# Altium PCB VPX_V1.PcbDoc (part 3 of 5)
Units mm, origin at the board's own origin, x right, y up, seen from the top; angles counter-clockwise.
Board outline 157.76 x 100.08 mm, 10 copper layers (Top Layer (PADS/SIG), Layer 2 (GND), Layer 3 (SIG), Layer 4 (SIG), Layer 5 (GND), Layer 6 (PWR), Layer 7 (GND), Layer 8 (SIG/PWR), Layer 9 (GND), Bottom Layer (PAD/SIG)), stack 1.614 mm thick; 383 components, 223 nets, 1313 pads, 1223 vias.
Unrouted connection lines stored in the file: 3.
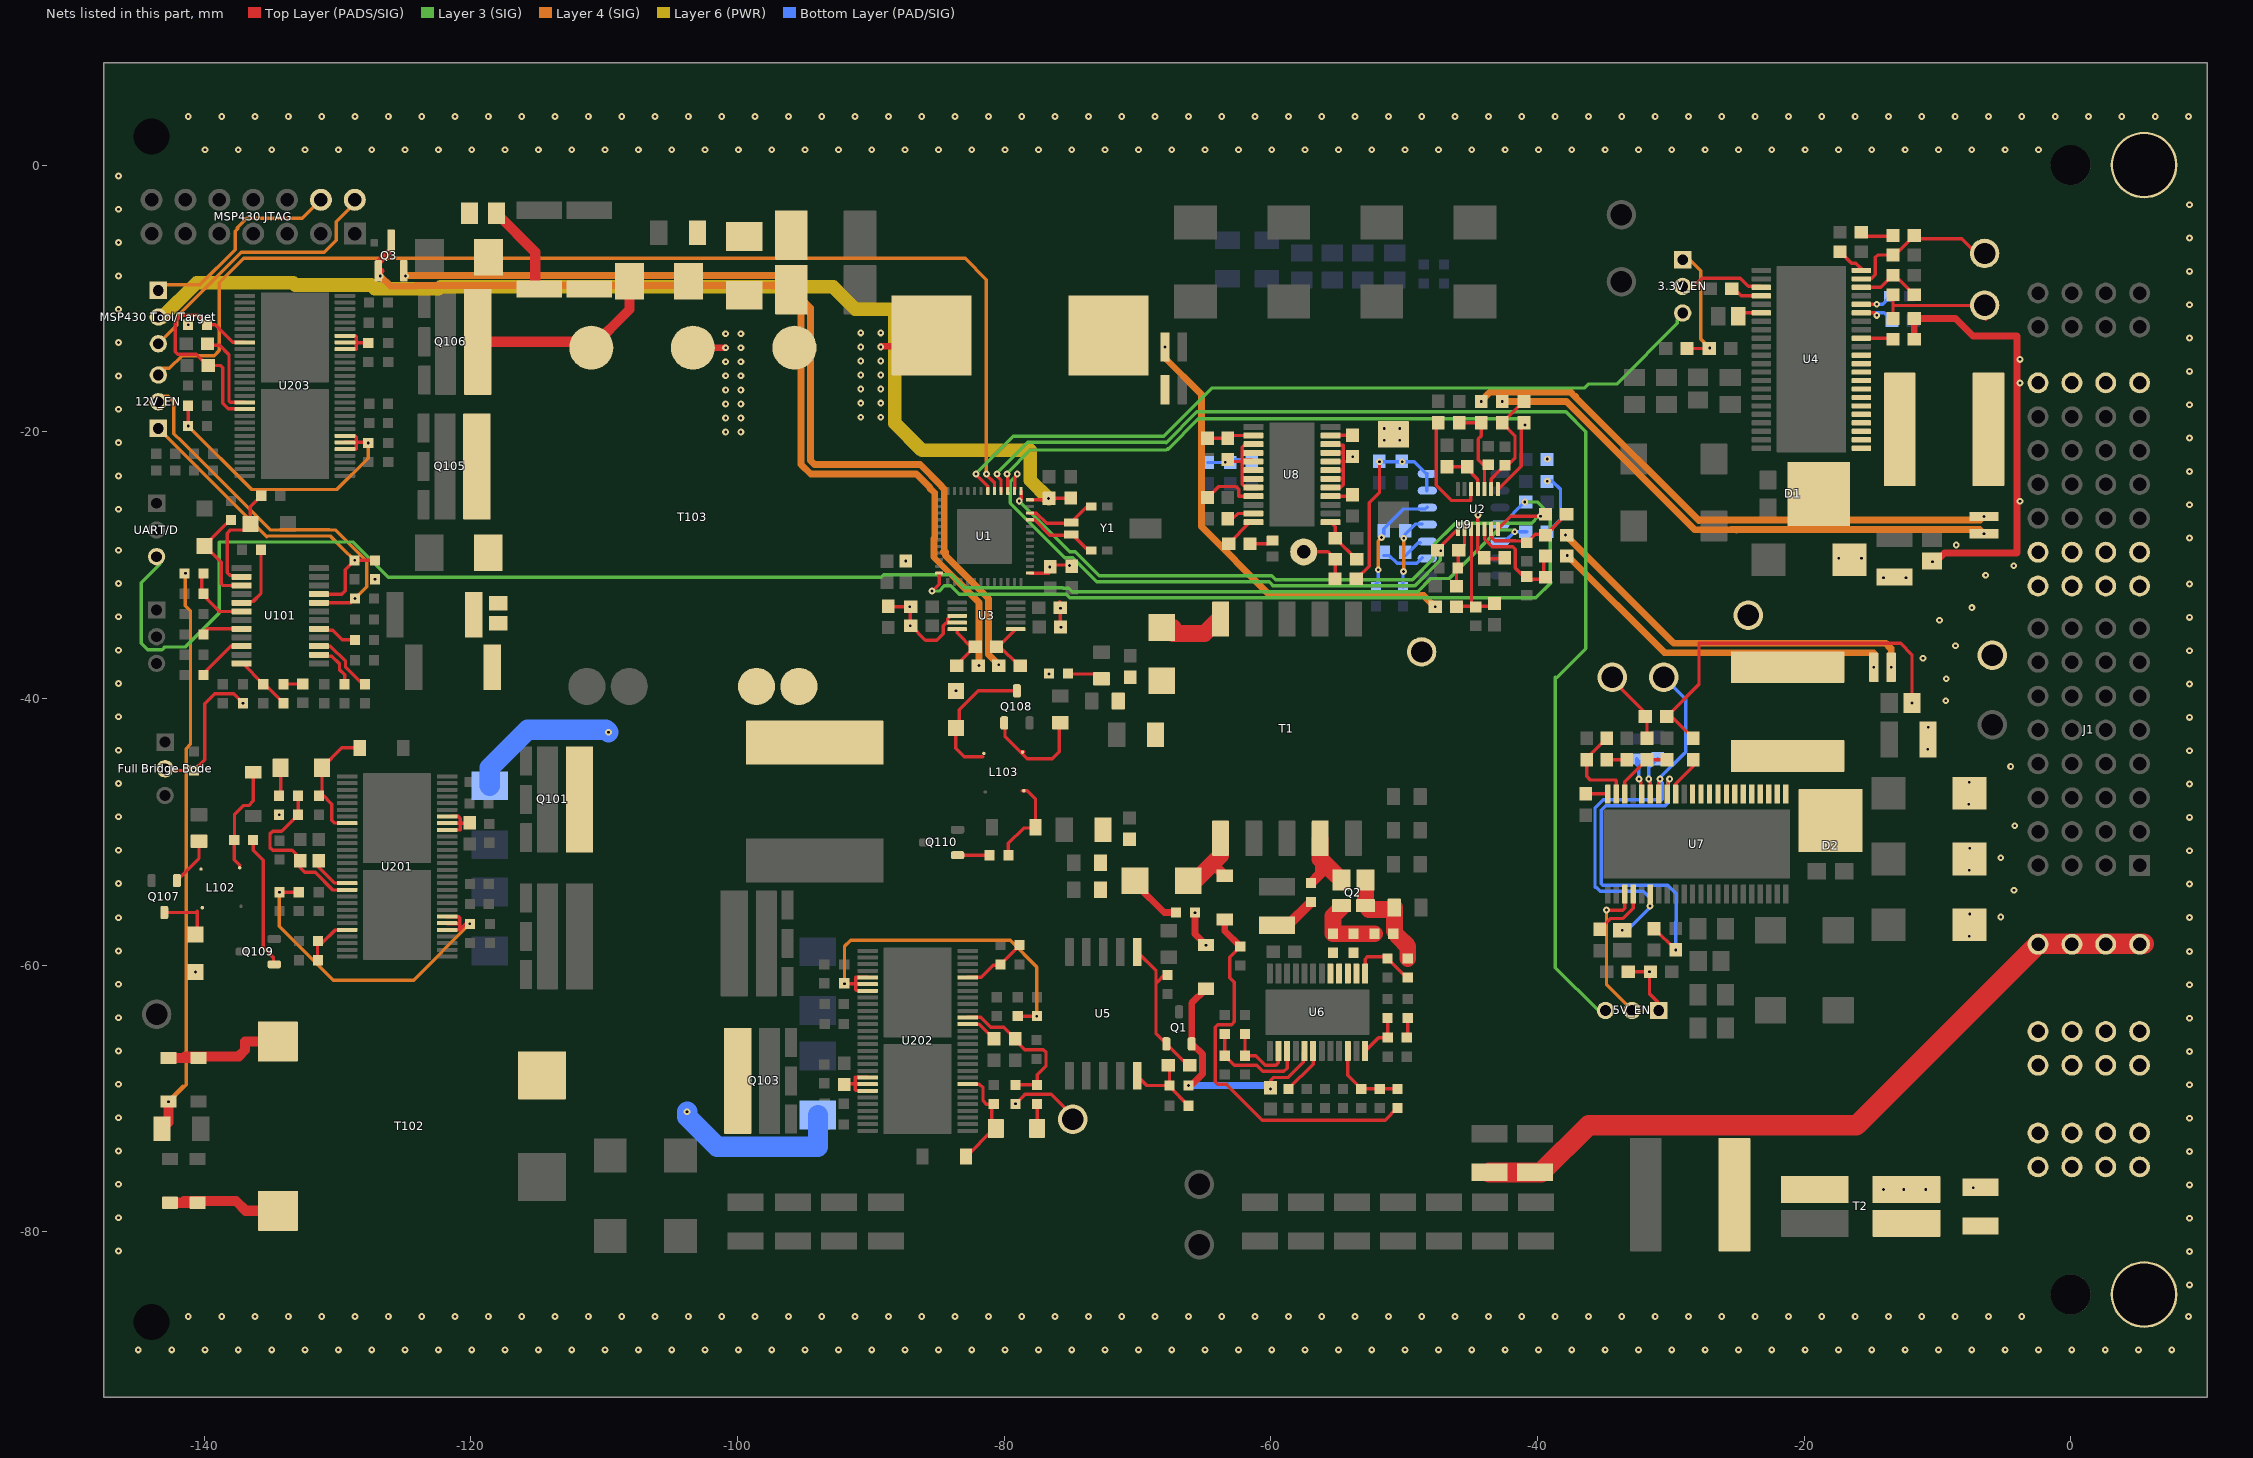
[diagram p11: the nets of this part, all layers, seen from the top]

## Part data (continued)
T1: library part CMP-0123192-1, "Transformer", Frequency_Fixed=500kHz, Manufacturer=Coilcraft, Operating Temperature Range=to, Voltage_Isolation_Vrms=2500Vrms
T2: library part CMP-0081219-1, "Coupled inductor, 0.001 ohm, AEC-Q200 Grade 1, SMD", Manufacturer="Laird-Signal Integrity Products", Supplier Part Number 1=240-2463-1-ND
T102: library part CMP-0122471-1, "Current Transformer 1:50", Manufacturer="Payton Planar", Operating Temperature Range=to
T103: library part CMP-0122726-1, "Transformer Vin-22-36V/500KHz/Full-Bridge, Vo=12V/26A Isolation=1500V, T/R=3:2", Manufacturer=Coilcraft, Operating Temperature Range=to, Voltage_Isolation_Vrms=1.5kV
U1: library part CMP-0066503-2, "MSP430FR5969 16 MHz Ultra-Low-Power Microcontroller featuring 64 KB FRAM, 2 KB SRAM, 40 IO, RGZ0048B (VQFN-48)", Alternate Manufacturer="Texas Instruments", Alternate PartNumber=MSP430FR5969IRGZT
U2: library part CMP-0037180-1, "Space-enhanced-product, quad, 40-V 4.5-MHz rail-to-rail input and output operational amplifier 14-SOT-23-THIN -55 to +125", Digikey Part Number=296-OPA4H199MDYYTSEP-ND, Input Bias Current=0.00001uA, Input Offset Voltage=0.125mV, Manufacturer="Texas Instruments", Max Dual Supply Voltage=20V, Max Supply Voltage=40V, Min Dual Supply Voltage=1.35V, Min Supply Voltage=2.7V, Mouser Part Number=595-OPA4H199MDYYTSEP, Nominal Supply Current=560uA, Operating Temperature Range="-55°C to +125°C", Output Current Per Channel=75mA, Voltage Gain=145dB
U3: library part CMP-0121240-1, "High-Accuracy, Radiation-Hardness-Assured (RHA) Remote and Local Temperature Sensor", Manufacturer="Texas Instruments", Max Supply Voltage=3.6V, Min Supply Voltage=1.7V, Operating Supply Current=3-400uA, Operating Temperature Range="-55°C to +125°C"
U4: library part CMP-0124169-1, "4.5V to 14V Input, 3A, Radiation Hardened Synchronous Buck Converter", Manufacturer="Texas Instruments", Max Supply Voltage=14V, Min Supply Voltage=4.5V, Nominal Supply Current=2.6mA, Operating Temperature Range="-55°C to +125°C", Switching Frequency=100-1000kHz
U5: library part CMP-0093806-3, "Radiation-hardness-assured (RHA) 0.4% accuracy, 2.4-V to 36-V adjustable shunt reference 10-CFP 25 to 25", Manufacturer="Texas Instruments", Max Supply Voltage=36V, Min Supply Voltage=2.475V, Mouser Part Number=595-TL1431U/EM, Operating Temperature Range="-55°C to +125°C", Output Voltage=2.5-36V
U6: library part CMP-0122233-2, "Radiation-Hardness-Assured 1-MHz Current Mode PWM Controller with Integrated Gate Driver", Manufacturer="Texas Instruments", Max Supply Voltage=14V, Min Supply Voltage=4.5V, Nominal Supply Current=5-22mA, Operating Temperature Range="-55°C to +125°C"
U7: library part CMP-0121219-1, "4.5-V to 14-V Input 12-A Radiation Hardened Synchronous Buck Converter", Manufacturer="Texas Instruments", Max Supply Voltage=14V, Min Supply Voltage=4.5V, Nominal Supply Current=8mA, Operating Temperature Range="-55°C to +125°C", Switching Frequency=100-1000kHz
U8: library part CMP-0122232-1, "2.25 V to 14-V Input, 2-A, Radiation Hardened LDO Regulator", Dropout Voltage=1000mV, Manufacturer="Texas Instruments", Max Supply Voltage=14V, Min Supply Voltage=2.25V, Nominal Supply Current=8-10mA, Operating Temperature Range="-55°C to +125°C", Output Voltage=0.6-13.9V
U9: library part CMP-0081980-1, "3.3-V to 5-V RS-485 Transceivers With +/-18-kV IEC ESD Protection, D0014A (SOIC-14)", Alternate Manufacturer="Texas Instruments", Alternate PartNumber=THVD1452DR, Operating Temperature Range="-40 to 125 C"
U101: library part CMP-0092938-1, Manufacturer="Texas Instruments", Operating Temperature Range=to
U201 U202: library part CMP-0120202-4, Manufacturer="Texas Instruments", Operating Temperature Range=to, PartNumber=TPS7H6015MDCATSEP
U203: library part CMP-0120202-4, Manufacturer="Texas Instruments", Operating Temperature Range=to, PartNumber=TPS7H6025MDCATSEP
Y1: library part CMP-0004695-4, "Crystal, 32.768 KHz, 7pF, SMD", Frequency_Fixed=32.768kHz, Load Capacitance="7 pF", Manufacturer="Micro Crystal AG"

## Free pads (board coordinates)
  round 1.524 hole 2.7 unplated: 3(-143.947,2.13) 4(-143.947,-86.77)

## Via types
v1: diameter 0.508, hole 0.203, Top Layer (PADS/SIG) to Bottom Layer (PAD/SIG), 943 vias
v2: diameter 0.5, hole 0.2, Top Layer (PADS/SIG) to Bottom Layer (PAD/SIG), tented both sides, 268 vias
v3: diameter 0.5, hole 0.2, Top Layer (PADS/SIG) to Bottom Layer (PAD/SIG), 12 vias

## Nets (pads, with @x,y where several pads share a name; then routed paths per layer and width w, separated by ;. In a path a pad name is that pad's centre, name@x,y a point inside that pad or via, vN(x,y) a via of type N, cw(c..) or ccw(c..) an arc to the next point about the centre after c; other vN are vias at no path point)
3.3_CurrentSense: R15.1 U1.3 U2.8 | length 47.8
  Top Layer (PADS/SIG) w0.254: U1.3@-79.718,-24.453 v1@-79.718,-23.162 ; U2.8@-42.969,-24.305 -42.926,-24.305 -41.275,-22.654 -41.275,-22.606 ; -41.221,-22.6 -41.221,-19.504 R15.1@-41.021,-19.304
  Layer 3 (SIG) w0.254: v1(-79.776,-23.172) -79.776,-23.123 -78.021,-21.368 -67.826,-21.368 -67.734,-21.276 ; -67.7,-21.31 -65.426,-19.036 -41.399,-19.036 v1(-40.937,-19.498)
3.3V: "MSP430 Tool/Target.2" C3.1 C4.1 C60.2 C88.1 C89.1 C99.2 C100.1 C126.1 R18.1 R19.1 R20.1 R21.1 R22.2 R24.1 R25.1 R26.1 R31.2 R80.1 U1.37 U1.48 U3.3 U3.4 U8.17 U8.18 U8.19 U8.20 U8.21 U8.22 U9.13 U9.14 | length 126
  Top Layer (PADS/SIG) w0.254: C60.2@-88.689,-33.087 -88.649,-33.128 v1(-87.069,-33.128) ; v1(-87.038,-34.542) R19.1@-87.038,-33.128 ; R18.1@-87.009,-34.513 -85.895,-35.627 -85.042,-35.627 -84.566,-35.151 -84.566,-34.556 -84.369,-34.359 ; -84.244,-34.336 -84.244,-34.057 -84,-33.813 U3.3@-83.514,-33.813 ; U1.37@-78.068,-30.603 C3.1@-76.655,-30.603 ; U1.48@-78.068,-25.103 -76.751,-25.103 v1(-76.661,-25.014) C88.1@-76.63,-24.982 -75.368,-24.982 C89.1@-75.147,-25.203 ; v1(-76.576,-30.154) -76.416,-29.994 -75.062,-29.994 -75.062,-30.001 v1(-75.1,-30.039) ; R20.1@-75.887,-33.231 R20.1@-75.887,-33.049 ; R20.1@-75.83,-33.231 R20.1@-75.83,-32.763 ; R21.1@-75.792,-34.511 R20.1@-75.792,-33.184 ; U8.17@-55.506,-24.188 -54.778,-24.188 -54.573,-23.983 -54.573,-23.51 ; U8.18@-55.506,-23.538 -54.601,-23.538 -54.573,-23.51 ; U8.19@-55.506,-22.888 -54.598,-22.888 -54.573,-22.863 ; U8.20@-55.506,-22.238 -54.573,-22.238 ; U8.21@-55.506,-21.588 -54.649,-21.588 -54.573,-21.664 ; U8.22@-55.034,-21.022 -54.573,-21.022 -54.573,-21.664 ; v1(-53.839,-21.888) -54.189,-22.238 -54.573,-22.238 ; R31.2@-53.58,-31.036 -52.621,-30.077 -52.621,-25.34 -51.859,-24.578 ; -51.84,-24.578 v1(-51.84,-22.254) ; -54.573,-23.51 -54.573,-22.863 ; -54.573,-22.863 -54.573,-22.238 ; -54.573,-22.238 -54.573,-21.664
  Layer 6 (PWR) w1.016: -143.426,-11.402 -143.125,-11.402 -140.553,-8.83 -133.305,-8.83 -133.139,-8.996 -127.475,-8.996 -127.187,-9.284 -122.38,-9.284 -122.234,-9.138 -92.822,-9.138 -91.148,-10.811 -88.181,-10.811 -88.181,-19.371 -86.149,-21.403 -78.041,-21.403 ; -78.021,-21.403 -78.041,-21.403 ; v1(-76.661,-25.014) -78.041,-23.634 -78.041,-21.403
  Bottom Layer (PAD/SIG) w0.254: v1(-51.84,-22.254) v1(-50.138,-22.254) -49.23,-22.254 U9.14@-48.303,-23.181 ; U9.13@-48.303,-24.451 -48.303,-23.197 U9.14@-48.259,-23.154 ; R80.1@-39.286,-27.626 R80.1@-39.253,-27.594 ; R80.1@-39.286,-27.499 -39.159,-27.499 -38.27,-26.61 -38.27,-24.324 -38.887,-23.707 v1(-39.253,-23.707)
  other v1: -75.737,-34.676 -75.766,-33.231 -87.383,-29.694 -39.253,-22.048 -51.478,-20.641 -50.335,-20.641 -51.478,-19.752 -50.335,-19.752
"3.3V CS+": L1.2 R3.1 R12.2 | length 42.5
  Top Layer (PADS/SIG) w0.508: v1(-6.515,-26.355) R3.1@-6.134,-26.355
  Layer 4 (SIG) w0.508: v1(-44.218,-17.732) -44.218,-17.699 -43.543,-17.024 -37.526,-17.024 -37.211,-17.339 ; -37.127,-17.339 -37.211,-17.339 ; -27.898,-26.652 -37.211,-17.339 ; -27.856,-26.61 -27.836,-26.63 -6.79,-26.63 v1(-6.515,-26.355)
3.3V_EN: 3.3V_EN.3 U1.6 | length 59.2
  Top Layer (PADS/SIG) w0.254: v1(-82.097,-23.172) -82.097,-23.22 -81.218,-24.098 U1.6@-81.218,-24.453
  Layer 3 (SIG) w0.254: v1(-82.097,-23.172) -82.097,-23.123 -79.324,-20.351 -68.024,-20.351 ; -68.03,-20.345 -64.41,-16.726 -36.482,-16.726 -36.182,-16.426 -34.055,-16.426 -29.507,-11.878 -29.507,-11.624
3.3V_OUT: 3.3V_Out.1 C25.1 C27.1 C29.1 J1.LP2 R3.2 R14.2 R35.1 R37.1 | length 73.4
  Top Layer (PADS/SIG) w0.508: R35.1@-11.738,-13.062 R37.1@-11.738,-11.509 -8.648,-11.509 -7.325,-12.833 -4.044,-12.833 -4.044,-29.1 -4.039,-29.105 -9.463,-29.105 -10.059,-29.701 C29.1@-10.401,-29.701
  Layer 4 (SIG) w0.508: v1@-42.582,-17.793 v1(-42.643,-17.732) -37.819,-17.732 -28.191,-27.36 -25.074,-27.36 -25.062,-27.372 ; -25.488,-27.338 -6.831,-27.338 v1(-6.515,-27.655)
  other v1: -14.054,-30.944 -12.361,-30.944 -10.367,-29.76 -17.394,-29.501 -15.701,-29.501 -8.582,-28.499 -3.807,-25.208 -3.807,-16.354 -3.807,-14.575
5V: 5V.1 C15.1 C66.1 C67.1 C68.1 C70.1 J1.P3 R9.2 R32.2 R41.1 R67.1 | length 58.4
  Top Layer (PADS/SIG) w0.254: R41.1@-28.315,-42.99 -29.94,-41.365 R67.1@-30.303,-41.365 -27.882,-38.944 -27.882,-35.877 -12.761,-35.877 -11.911,-36.727 v1(-11.911,-40.352)
  Layer 4 (SIG) w0.508: v1(-37.889,-27.753) -29.78,-35.863 -13.905,-35.863 -13.505,-36.262 ; v1(-13.472,-37.671) -13.472,-36.262
  other v1: -7.612,-57.833 -5.246,-56.388 -7.574,-56.178 -4.261,-54.386 -7.612,-52.888 -5.246,-51.943 -7.574,-51.233 -4.196,-49.557 -7.649,-47.936 -7.61,-46.281 -4.512,-45.102 -10.734,-43.818 -10.695,-42.163 -9.382,-40.182 -9.344,-38.527 -11.078,-36.991 -8.648,-36.046 -9.848,-34.138 -7.418,-33.193 -6.388,-30.77 -4.275,-30.05
"5V CS+": L2.2 R5.2 R32.1 | length 27.1
  Layer 4 (SIG) w0.508: v1(-37.762,-29.277) -30.469,-36.571 -14.772,-36.571 v1(-14.772,-37.671)
5V_CurrentSense: R11.1 U1.1 U2.7 | length 48.8
  Top Layer (PADS/SIG) w0.254: v1(-78.861,-25.203) -78.718,-25.06 U1.1@-78.718,-24.453 ; U2.7@-42.969,-27.305 -42,-26.336 v1(-39.775,-26.336) R11.1@-39.775,-26.185
  Layer 3 (SIG) w0.254: v1@-78.861,-25.383 v1(-78.861,-25.203) -75.073,-28.991 -74.665,-28.991 -72.86,-30.796 -59.926,-30.796 -59.632,-31.09 -49.368,-31.09 -47.842,-29.564 -47.842,-28.562 -46.144,-26.864 -40.429,-26.864 v1@-39.921,-26.356 ; v1@-39.858,-26.419 v1(-39.775,-26.336)
5V_EN: 5V_EN.3 U1.4 | length 93.6
  Top Layer (PADS/SIG) w0.254: v1@-80.55,-23.285 -80.231,-23.603 -80.231,-24.44 U1.4@-80.218,-24.453
  Layer 3 (SIG) w0.254: v1(-80.533,-23.167) -80.533,-23.106 -78.231,-20.805 -67.861,-20.805 ; -67.849,-20.817 -65.544,-18.513 -37.858,-18.513 -36.365,-20.006 ; -38.651,-38.421 -38.651,-60.193 5V_EN.3@-35.441,-63.403 ; -38.524,-38.421 -36.365,-36.262 -36.365,-20.084
"12V CS+": L101.2 R1.1 R2.1 R4.2 | length 34.6
  Layer 4 (SIG) w0.508: v1@-67.988,-13.656 -67.988,-14.418 -65.257,-17.149 ; v1@-67.936,-13.656 v1(-67.936,-13.648) ; -65.194,-17.212 -65.194,-27.118 -60.041,-32.271 -48.532,-32.271 v1(-47.668,-33.135)
12V_CurrentSense: R10.1 U1.2 U2.1 | length 41.8
  Top Layer (PADS/SIG) w0.254: U1.2@-79.211,-24.288 -79.211,-23.444 -79.003,-23.236 v1(-79.003,-23.172) ; R10.1@-47.336,-28.672 U2.1@-45.969,-27.305
  Layer 3 (SIG) w0.254: v1(-79.003,-23.172) -79.003,-23.22 -79.536,-23.753 -79.536,-25.35 -75.441,-29.445 -74.853,-29.445 -73.048,-31.25 -60.114,-31.25 -59.86,-31.504 -59.86,-31.544 -49.18,-31.544 -47.287,-29.651 v1@-47.287,-29.023
  other v1: -47.261,-28.927
12V_EN: 12V_EN.3 U1.5 | length 85.3
  Top Layer (PADS/SIG) w0.254: v1(-81.323,-23.172) -81.323,-23.22 -80.718,-23.825 U1.5@-80.718,-24.453
  Layer 4 (SIG) w0.254: 12V_EN.3@-143.426,-15.434 12V_EN.3@-143.331,-15.339 ; 12V_EN.3@-143.426,-15.244 -142.601,-15.244 -141.648,-14.291 -139.235,-14.291 -138.854,-13.91 -138.854,-8.83 ; -138.856,-8.828 -137.022,-6.994 -82.916,-6.994 -81.323,-8.587 v1@-81.323,-23.054
+12Vp: 12Vp_EXT.1 D5.2 R78.2 R201.1 R214.1 | length 8
  Top Layer (PADS/SIG) w0.254: v1(-79.148,-70.409) -78.529,-69.79 -78.434,-69.695 -76.465,-69.695 12Vp_EXT.1@-75.227,-70.933 ; 12Vp_EXT.1@-75.29,-70.997 12Vp_EXT.1@-74.973,-71.314
  Top Layer (PADS/SIG) w0.508: v1(-65.675,-56.065) -65.675,-57.676 v1(-64.848,-58.504)
  other v1: -134.367,-48.723
+12Vs: 12Vs_EXT.1 C26.1 C28.2 C96.1 C97.1 C98.1 D111.1 D112.1 R23.1 R77.2 R107.2 R227.1 U2.4 U8.3 U8.4 U8.5 U8.6 U8.7 U8.8 | length 16.4
  Top Layer (PADS/SIG) w0.254: R23.1@-63.211,-22.087 -63.061,-22.238 -62.14,-22.238 ; U8.8@-61.306,-24.188 -61.883,-24.188 -62.14,-23.931 -62.14,-22.238 ; U8.4@-61.306,-21.588 -61.309,-21.585 -62.14,-21.585 ; U8.3@-61.306,-20.938 -61.899,-20.938 -62.14,-21.178 -62.14,-21.585 ; v1@-44.493,-26.229 -44.469,-26.253 U2.4@-44.469,-27.305 -44.469,-29.047 C28.2@-44.023,-29.493 ; C28.2@-43.985,-29.455 -43.909,-29.531 C26.1@-42.461,-29.531 ; -62.14,-22.238 U8.5@-61.306,-22.238 -61.461,-22.083 -62.14,-22.083 -62.14,-21.585
  Bottom Layer (PAD/SIG) w0.254: C96.1@-64.721,-22.308 C97.1@-63.441,-22.308 ; C97.1@-63.215,-22.083 -61.64,-22.083 C98.1@-61.415,-22.308
  other v1: -140.632,-60.519 -83.609,-39.434 -76.624,-38.167 -127.18,-31.071 -44.461,-26.248 -63.416,-22.292 -141.19,-11.984
AVDD: C75.1 LDOCAP.1 U7.6 U7.38 | length 31.1
  Top Layer (PADS/SIG) w0.254: v1(-33.64,-57.383) C75.1@-33.263,-57.383 ; U7.38@-30.906,-47.174 -30.897,-47.165 v1@-30.897,-46.219
  Bottom Layer (PAD/SIG) w0.254: v1(-33.64,-57.383) -33.263,-57.383 -31.59,-55.71 -31.59,-54.952 -32.064,-54.478 -35.286,-54.478 -35.585,-54.179 -35.679,-54.179 -35.679,-48.197 -35.075,-47.593 -30.659,-47.593 -30.636,-47.57 -30.636,-46.32 v1@-30.79,-46.166 ; v1(-30.809,-46.042) -30.809,-45.945 -28.969,-44.105 -28.968,-44.105 -28.872,-44.009 -28.872,-40.07 LDOCAP.1@-30.53,-38.412
  other v1: -31.552,-55.562
"Bias SYNC": R63.2 U6.18 | length 3.7
  Top Layer (PADS/SIG) w0.254: R63.2@-58.676,-69.171 R63.2@-58.676,-69.289 -56.824,-67.437 U6.18@-56.824,-66.443
"Bias VSENSE": C57.2 R62.1 R66.2 U6.22 | length 6
  Top Layer (PADS/SIG) w0.254: U6.22@-54.224,-66.443 -54.224,-68.272 C57.2@-53.207,-69.289 R66.2@-51.819,-69.289 R62.1@-50.505,-69.289
Chassis: C1.2 C2.2 J1.LP1 J2.1 J4.1 | length 55.7
  Top Layer (PADS/SIG) w1.524: C1.2@-43.609,-75.55 C2.2@-40.175,-75.55 -39.715,-75.55 -36.168,-72.004 -16.388,-72.004 ; -16.256,-72.009 -16.067,-72.009 J1.LP1@-2.456,-58.398 ; J1.LP1@-2.126,-58.398 J1.LP1@5.494,-58.398
  other v1: -144.924,-88.86 -142.424,-88.86 -139.924,-88.86 -137.424,-88.86 -134.924,-88.86 -132.424,-88.86 -129.924,-88.86 -127.424,-88.86 -124.924,-88.86 -122.424,-88.86 -119.924,-88.86 -117.424,-88.86 -114.924,-88.86 -112.424,-88.86 -109.924,-88.86 -107.424,-88.86 -104.924,-88.86 -102.424,-88.86 -99.924,-88.86 -97.424,-88.86 -94.924,-88.86 -92.424,-88.86 -89.924,-88.86 -87.424,-88.86 -84.924,-88.86 -82.424,-88.86 -79.924,-88.86 -77.424,-88.86 -74.924,-88.86 -72.424,-88.86 -69.924,-88.86 -67.424,-88.86 -64.924,-88.86 -62.424,-88.86 -59.924,-88.86 -57.424,-88.86 -54.924,-88.86 -52.424,-88.86 -49.924,-88.86 -47.424,-88.86 -44.924,-88.86 -42.424,-88.86 -39.924,-88.86 -37.424,-88.86 -34.924,-88.86 -32.424,-88.86 -29.924,-88.86 -27.424,-88.86 -24.924,-88.86 -22.424,-88.86 -19.924,-88.86 -17.424,-88.86 -14.924,-88.86 -12.424,-88.86 -9.924,-88.86 -7.424,-88.86 -4.924,-88.86 -2.424,-88.86 0.076,-88.86 2.576,-88.86 5.076,-88.86 7.576,-88.86 -141.174,-86.36 -138.674,-86.36 -136.174,-86.36 -133.674,-86.36 -131.174,-86.36 -128.674,-86.36 -126.174,-86.36 -123.674,-86.36 -121.174,-86.36 -118.674,-86.36 -116.174,-86.36 -113.674,-86.36 -111.174,-86.36 -108.674,-86.36 -106.174,-86.36 -103.674,-86.36 -101.174,-86.36 -98.674,-86.36 -96.174,-86.36 -93.674,-86.36 -91.174,-86.36 -88.674,-86.36 -86.174,-86.36 -83.674,-86.36 -81.174,-86.36 -78.674,-86.36 -76.174,-86.36 -73.674,-86.36 -71.174,-86.36 -68.674,-86.36 -66.174,-86.36 -63.674,-86.36 -61.174,-86.36 -58.674,-86.36 -56.174,-86.36 -53.674,-86.36 -51.174,-86.36 -48.674,-86.36 -46.174,-86.36 -43.674,-86.36 -41.174,-86.36 -38.674,-86.36 -36.174,-86.36 -33.674,-86.36 -31.174,-86.36 -28.674,-86.36 -26.174,-86.36 -23.674,-86.36 -21.174,-86.36 -18.674,-86.36 -16.174,-86.36 -13.674,-86.36 -11.174,-86.36 -8.674,-86.36 -6.174,-86.36 -3.674,-86.36 8.826,-86.36 8.91,-83.984 8.91,-81.484 -146.411,-81.444 8.91,-78.984 -146.411,-78.944 8.91,-76.484 -146.411,-76.444 8.91,-73.984 -146.411,-73.944 8.91,-71.484 -146.411,-71.444 8.91,-68.984 -146.411,-68.944 8.91,-66.484 -146.411,-66.444 8.91,-63.984 -146.411,-63.944 8.91,-61.484 -146.411,-61.444 8.91,-58.984 -146.411,-58.944 -146.411,-56.444 8.91,-56.425 8.91,-53.925 -146.411,-53.885 8.91,-51.425 -146.411,-51.385 8.91,-48.925 -146.411,-48.885 8.91,-46.425 -146.411,-46.385 8.91,-43.925 -146.411,-43.885 8.91,-41.425 -146.411,-41.385 8.91,-38.925 -146.411,-38.885 8.91,-36.425 -146.411,-36.385 8.91,-33.925 -146.411,-33.885 8.91,-31.425 -146.411,-31.385 -146.411,-28.885 8.91,-27.977 -146.411,-25.818 8.91,-25.477 -146.411,-23.318 8.91,-22.977 -146.411,-20.818 8.91,-20.477 -146.411,-18.318 8.91,-17.977 -146.411,-15.818 8.91,-15.477 -146.411,-13.318 8.91,-12.977 -146.411,-10.818 8.91,-10.477 -146.411,-8.318 8.91,-7.977 -146.411,-5.818 8.91,-5.477 -146.411,-3.318 8.91,-2.977 -146.411,-0.818 -139.924,1.14 -137.424,1.14 -134.924,1.14 -132.424,1.14 -129.924,1.14 -127.424,1.14 -124.924,1.14 -122.424,1.14 -119.924,1.14 -117.424,1.14 -114.924,1.14 -112.424,1.14 -109.924,1.14 -107.424,1.14 -104.924,1.14 -102.424,1.14 -99.924,1.14 -97.424,1.14 -94.924,1.14 -92.424,1.14 -89.924,1.14 -87.424,1.14 -84.924,1.14 -82.424,1.14 -79.924,1.14 -77.424,1.14 -74.924,1.14 -72.424,1.14 -69.924,1.14 -67.424,1.14 -64.924,1.14 -62.424,1.14 -59.924,1.14 -57.424,1.14 -54.924,1.14 -52.424,1.14 -49.924,1.14 -47.424,1.14 -44.924,1.14 -42.424,1.14 -39.924,1.14 -37.424,1.14 -34.924,1.14 -32.424,1.14 -29.924,1.14 -27.424,1.14 -24.924,1.14 -22.424,1.14 -19.924,1.14 -17.424,1.14 -14.924,1.14 -12.424,1.14 -9.924,1.14 -7.424,1.14 -4.924,1.14 -2.424,1.14 -141.174,3.64 -138.674,3.64 -136.174,3.64 -133.674,3.64 -131.174,3.64 -128.674,3.64 -126.174,3.64 -123.674,3.64 -121.174,3.64 -118.674,3.64 -116.174,3.64 -113.674,3.64 -111.174,3.64 -108.674,3.64 -106.174,3.64 -103.674,3.64 -101.174,3.64 -98.674,3.64 -96.174,3.64 -93.674,3.64 -91.174,3.64 -88.674,3.64 -86.174,3.64 -83.674,3.64 -81.174,3.64 -78.674,3.64 -76.174,3.64 -73.674,3.64 -71.174,3.64 -68.674,3.64 -66.174,3.64 -63.674,3.64 -61.174,3.64 -58.674,3.64 -56.174,3.64 -53.674,3.64 -51.174,3.64 -48.674,3.64 -46.174,3.64 -43.674,3.64 -41.174,3.64 -38.674,3.64 -36.174,3.64 -33.674,3.64 -31.174,3.64 -28.674,3.64 -26.174,3.64 -23.674,3.64 -21.174,3.64 -18.674,3.64 -16.174,3.64 -13.674,3.64 -11.174,3.64 -8.674,3.64 -6.174,3.64 -3.674,3.64 -1.174,3.64 1.326,3.64 3.826,3.64 6.326,3.64 8.826,3.64
D: R80.2 U9.5 UART/D.3 | length 122.1
  Layer 3 (SIG) w0.254: UART/D.3@-143.299,-29.912 -144.705,-31.318 -144.705,-35.881 -144.236,-36.35 -143.148,-36.35 -142.945,-36.146 -141.405,-36.146 -138.854,-33.595 -138.854,-28.276 -128.813,-28.276 -126.181,-30.907 -89.194,-30.907 -89.018,-30.732 -83.957,-30.732 -82.985,-31.704 -75.608,-31.704 -75.569,-31.742 -75.149,-31.742 -74.894,-31.998 -48.977,-31.998 -47.987,-31.008 -46.605,-31.008 -42.969,-27.372 v1@-41.699,-27.372
  Bottom Layer (PAD/SIG) w0.254: U9.5@-42.809,-28.234 -42.434,-28.234 v1(-41.699,-27.499) R80.2@-40.886,-27.499 R80.2@-40.81,-27.499
DE: R30.1 U1.24 U9.4 | length 58.9
  Top Layer (PADS/SIG) w0.254: v1(-85.403,-31.95) -85.391,-31.95 -84.868,-31.428 U1.24@-84.868,-30.603
  Layer 3 (SIG) w0.254: v1(-85.403,-31.95) -84.874,-31.95 -84.475,-31.551 -83.994,-31.551 -83.388,-32.158 ; -83.355,-32.196 -75.337,-32.196 -75.082,-32.452 -40.122,-32.452 -38.979,-31.309 -39.032,-31.256 -39.032,-26.258 -40.019,-25.27 v1(-40.947,-25.27)
  Bottom Layer (PAD/SIG) w0.254: U9.4@-42.809,-26.964 -42.641,-26.964 v1(-40.947,-25.27)
EN: R49.1 R52.2 U6.15 | length 8.2
  Top Layer (PADS/SIG) w0.254: R49.1@-63.451,-65.17 R52.2@-63.451,-66.796 -62.736,-67.51 -61.057,-67.51 -60.593,-67.974 -59.012,-67.974 -58.774,-67.736 U6.15@-58.774,-66.443
"Input Return": C6.2 J1.P1 T2.1
Input_Supply: C6.1 J1.P2 T2.2
  other v1: -14.045,-76.832 -12.521,-76.832 -10.87,-76.832 -7.314,-76.705
"Net3.3V Bode_1": "3.3V Bode.1" R37.2 R38.2 | length 9
  Top Layer (PADS/SIG) w0.254: R37.2@-13.338,-11.509 -13.338,-10.458 ; R38.2@-13.338,-9.964 -13.338,-10.458 ; -6.389,-11.564 -7.418,-10.535 -13.261,-10.535 -13.338,-10.458
"Net3.3V Comp_1": "3.3V Comp.1" C35.1 R44.2 U4.43 | length 12.2
  Top Layer (PADS/SIG) w0.254: U4.43@-15.704,-8.543 -14.981,-8.543 -14.652,-8.214 -14.652,-6.91 -14.492,-6.75 C35.1@-13.338,-6.75 -13.199,-6.75 R44.2@-11.738,-5.289 ; C35.1@-13.338,-6.981 C35.1@-13.274,-6.981 ; R44.2@-11.738,-5.52 -8.177,-5.52 -6.389,-7.308
Net3.3V_EN_1: 3.3V_EN.1 R33.1 R34.1 | length 9.7
  Top Layer (PADS/SIG) w0.254: R34.1@-28.782,-13.758 R33.1@-27.108,-13.758
  Layer 4 (SIG) w0.254: 3.3V_EN.1@-29.107,-6.563 -27.754,-7.916 -27.754,-13.048 v1(-27.08,-13.722)
Net3.3V_EN_2: 3.3V_EN.2 U4.3 | length 6.5
  Top Layer (PADS/SIG) w0.254: 3.3V_EN.2@-29.107,-9.103 -28.293,-9.103 -27.669,-8.478 -24.798,-8.478 -24.173,-9.103 -23.279,-9.103 U4.3@-23.204,-9.178
"Net5V Bode_1": "5V Bode.1" R67.2 R68.2 | length 5.6
  Top Layer (PADS/SIG) w0.254: -34.384,-38.42 -34.384,-38.586 -31.903,-41.067 R67.2@-31.903,-41.365 -31.786,-41.481 R68.2@-31.786,-42.99
Net5V_EN_1: 5V_EN.1 R36.1 R39.1 | length 5
  Top Layer (PADS/SIG) w0.254: R39.1@-33.195,-60.51 v1(-31.596,-60.51) -31.596,-62.168 5V_EN.1@-30.361,-63.403
Net5V_EN_2: 5V_EN.2 U7.3 | length 10.8
  Top Layer (PADS/SIG) w0.254: v1(-34.817,-55.875) -33.59,-55.875 -33.446,-55.731 U7.3@-33.446,-54.674
  Layer 4 (SIG) w0.254: v1(-34.817,-55.875) -34.817,-61.487 5V_EN.2@-32.901,-63.403
Net12V_EN_1: 12V_EN.1 C101.1 R107.1 U101.9 | length 25.4
  Top Layer (PADS/SIG) w0.254: U101.9@-131.381,-32.181 -129.667,-32.181 -129.412,-31.926 -129.412,-30.363 -128.704,-29.655 v1(-128.704,-29.648) R107.1@-127.18,-29.648
  Layer 4 (SIG) w0.254: 12V_EN.1@-143.426,-19.244 12V_EN.1@-143.426,-19.752 -135.298,-27.88 ; -135.171,-27.822 -130.53,-27.822 -129.583,-28.769 v1(-128.704,-29.648)
Net12V_EN_2: 12V_EN.2 R76.1 U101.8 | length 28.1
  Top Layer (PADS/SIG) w0.25: U101.8@-131.381,-32.831 -128.993,-32.831 v1(-128.678,-32.517)
  Layer 4 (SIG) w0.25: 12V_EN.2@-143.426,-17.244 -143.331,-17.339 -142.664,-17.339 -142.257,-17.746 -142.257,-20.159 -141.648,-20.768 ; -141.647,-20.767 -135.044,-27.37 ; -134.919,-27.37 -134.282,-27.37 ; -134.282,-27.346 -130.599,-27.346 ; -130.599,-27.37 -130.163,-27.37 -127.805,-29.728 -127.805,-31.643 v1(-128.678,-32.517)
NetC14_2: C14.2 U1.45 Y1.2 | length 5.2
  Top Layer (PADS/SIG) w0.254: U1.45@-78.068,-26.603 -77.715,-26.603 -76.565,-27.753 Y1.2@-75.227,-27.753 ; Y1.2@-74.954,-27.695 -74.904,-27.695 C14.2@-73.576,-29.023
NetC16_2: C16.2 U1.46 Y1.1 | length 5.2
  Top Layer (PADS/SIG) w0.254: U1.46@-78.068,-26.103 -77.573,-26.103 -76.812,-26.864 Y1.1@-75.227,-26.864 ; Y1.1@-74.954,-26.795 -73.753,-25.594 C16.2@-73.449,-25.594
NetC30_1: C30.1 C31.1 U2.11 | length 3.6
  Top Layer (PADS/SIG) w0.254: C30.1@-46.906,-22.673 -46.869,-22.636 C31.1@-45.266,-22.636 ; C31.1@-45.342,-22.713 -44.469,-23.586 U2.11@-44.469,-24.305
NetC32_1: C32.1 U4.44 | length 2.3
  Top Layer (PADS/SIG) w0.254: C32.1@-17.304,-6.506 -16.444,-7.366 -16.129,-7.366 U4.44@-15.621,-7.874
NetC33_2: C33.2 U4.40 | length 2.3
  Top Layer (PADS/SIG) w0.254: U4.40@-15.704,-10.448 -15.696,-10.439 v1@-14.71,-10.439
  Bottom Layer (PAD/SIG) w0.254: v1@-14.71,-10.439 v1(-14.552,-10.439) -14.098,-10.439 C33.2@-13.632,-9.973
NetC34_1: C34.1 U4.6 | length 1.9
  Top Layer (PADS/SIG) w0.254: C34.1@-24.947,-11.352 -24.947,-11.191 -24.597,-11.191 -24.489,-11.083 U4.6@-23.204,-11.083
NetC36_1: C36.1 R44.1 | length 2.5
  Top Layer (PADS/SIG) w0.254: C36.1@-15.704,-5.045 -15.415,-5.334 R44.1@-13.335,-5.334
NetC37_1: C37.1 Q1.1 R46.1 U5.1 | length 11.4
  Top Layer (PADS/SIG) w0.254: U5.1@-70.017,-59.021 -68.601,-60.437 -68.601,-61.366 ; R46.1@-67.642,-60.7 -67.935,-60.7 -68.601,-61.366 ; C37.1@-66.169,-67.507 -66.236,-67.507 Q1.1@-67.83,-65.913 -68.601,-65.142 -68.601,-61.366
NetC37_2: C37.2 R47.1 R48.2 U5.10 | length 6.4
  Top Layer (PADS/SIG) w0.254: U5.10@-70.017,-68.301 -69.287,-69.031 R47.1@-67.591,-69.031 ; C37.2@-67.591,-67.507 R47.1@-67.591,-69.031 ; R48.2@-66.169,-70.555 -67.591,-69.133 R47.1@-67.591,-69.031
NetC43_1: C43.1 D5.1 Q1.2 R47.2 U6.17 | length 19.3
  Top Layer (PADS/SIG) w0.254: v1(-60.022,-69.289) -60.022,-68.659 -59.791,-68.428 -58.7,-68.428 -57.572,-67.3 -57.572,-66.541 U6.17@-57.474,-66.443
  Top Layer (PADS/SIG) w0.508: R47.2@-66.124,-68.987 v1(-66.169,-69.031) -65.987,-69.031 -65.126,-68.17 -65.126,-66.683 Q1.2@-65.829,-65.98 ; Q1.2@-65.93,-65.913 -65.93,-62.861 D5.1@-64.848,-61.779
  Bottom Layer (PAD/SIG) w0.508: v1(-66.169,-69.031) -60.28,-69.031 v1(-60.022,-69.289)
NetC44_1: C44.1 C45.2 C46.2 D6.1 R54.2 R77.1 | length 2.7
  Top Layer (PADS/SIG) w0.254: R77.1@-75.216,-38.136 R77.1@-75.1,-38.136 ; R77.1@-75.1,-38.167 -73.052,-38.167 C45.2@-72.687,-38.532
NetC47_1: C47.1 Q2.2 T1.4 | length 5.4
  Top Layer (PADS/SIG) w0.762: C47.1@-56.974,-53.842 -56.291,-53.159 -56.291,-52.035
  Top Layer (PADS/SIG) w1.27: T1.4@-56.291,-50.492 -56.291,-52.035 Q2.2@-55.01,-53.317
NetC47_2: C47.2 R59.2 | length 3.3
  Top Layer (PADS/SIG) w0.762: R59.2@-59.514,-57.019 -58.729,-57.019 C47.2@-56.974,-55.264
NetC48_1: C48.1 R57.2 U6.1 | length 4.9
  Top Layer (PADS/SIG) w0.254: U6.1@-52.924,-60.643 -52.924,-59.552 -52.748,-59.376 C48.1@-51.249,-59.376 ; C48.1@-51.249,-59.505 -49.981,-60.773 R57.2@-49.7,-60.773
NetC49_1: C49.1 C50.2 C51.2 D7.1 R60.2 R78.1 | length 3.8
  Top Layer (PADS/SIG) w0.508: D7.1@-70.017,-54.037 -67.989,-56.065 R78.1@-67.098,-56.065
NetC52_2: C52.2 D8.1 R62.2 | length 29.6
  Top Layer (PADS/SIG) w0.254: C52.2@-62.281,-58.617 -63.085,-59.421 -63.085,-60.96 -62.743,-61.302 -62.743,-64.264 -62.941,-64.462 -63.967,-64.462 -64.159,-64.654 -64.159,-68.735 -63.967,-68.926 -63.289,-68.926 -63.289,-68.97 -60.632,-71.627 -51.421,-71.627 R62.2@-50.505,-70.711 ; R62.2@-50.505,-70.806 R62.2@-50.462,-70.806
  Top Layer (PADS/SIG) w0.508: D8.1@-63.451,-56.572 -63.451,-57.447 C52.2@-62.281,-58.617
NetC55_1: C55.1 R61.1 | length 1.5
  Top Layer (PADS/SIG) w0.254: R61.1@-49.803,-65.437 -49.725,-65.359 C55.1@-49.725,-63.975
NetC56_1: C56.1 R61.2 U6.24 | length 3.6
  Top Layer (PADS/SIG) w0.254: U6.24@-52.924,-66.443 -51.918,-65.437 R61.2@-51.226,-65.437 -51.226,-63.999 C56.1@-51.249,-63.975
NetC61_1: C61.1 R17.2 U3.6 | length 4.1
  Top Layer (PADS/SIG) w0.254: C61.1@-80.561,-36.135 C61.1@-80.436,-36.135 ; U3.6@-79.114,-34.813 C61.1@-80.436,-36.135 ; R17.2@-78.91,-37.532 -80.307,-36.135 C61.1@-80.436,-36.135
NetC61_2: C61.2 R16.2 U3.5 | length 3.8
  Top Layer (PADS/SIG) w0.254: U3.5@-83.514,-34.813 -83.514,-35.087 C61.2@-82.339,-36.262 ; R16.2@-83.482,-37.405 C61.2@-82.339,-36.262 ; C61.2@-82.161,-36.135 -82.212,-36.135 C61.2@-82.339,-36.262
NetC73_1: C73.1 U7.44 | length 1.7
  Top Layer (PADS/SIG) w0.254: C73.1@-36.367,-47.152 -34.737,-47.152 U7.44@-34.716,-47.174
NetC74_2: C74.2 U7.40 | length 3.3
  Top Layer (PADS/SIG) w0.254: v1(-32.389,-46.042) -32.237,-46.195 -32.237,-47.174 U7.40@-32.176,-47.174
  Bottom Layer (PAD/SIG) w0.254: -32.57,-44.991 C74.2@-32.57,-44.54 -32.389,-44.72 v1(-32.389,-46.042)
NetC76_1: C76.1 R74.2 U7.43 | length 6.5
  Top Layer (PADS/SIG) w0.254: R74.2@-34.803,-42.99 -36.311,-44.498 C76.1@-36.311,-44.59 -36.311,-45.841 -36.03,-46.122 -34.125,-46.122 -34.079,-46.168 U7.43@-34.079,-46.803
NetC77_1: C77.1 R74.1 | length 1.5
  Top Layer (PADS/SIG) w0.254: R74.1@-34.803,-44.59 C77.1@-33.295,-44.59
NetC90_1: C90.1 R4.1 R6.1 U2.3 | length 8.8
  Top Layer (PADS/SIG) w0.254: R4.1@-46.017,-33.087 C90.1@-44.632,-33.087 ; U2.3@-44.969,-27.626 U2.3@-44.969,-27.305 ; U2.3@-44.946,-27.626 -44.946,-32.773 C90.1@-44.632,-33.087 ; R6.1@-43.223,-32.833 -43.489,-33.099 -44.62,-33.099 C90.1@-44.632,-33.087
NetC91_1: C91.1 R5.1 R7.1 U2.5 | length 8.8
  Top Layer (PADS/SIG) w0.254: U2.5@-43.969,-27.305 -43.946,-27.328 -43.946,-28.078 -43.396,-28.628 -41.851,-28.628 -41.659,-28.82 -41.659,-30.223 C91.1@-40.894,-30.988 ; C91.1@-40.683,-30.813 -40.441,-31.055 R7.1@-39.413,-31.055 ; R5.1@-39.54,-29.404 -39.54,-30.775 R7.1@-39.394,-30.921
NetC92_1: C92.1 R8.1 R10.2 U2.2 | length 4.5
  Top Layer (PADS/SIG) w0.254: R8.1@-46.071,-31.589 -46.071,-30.271 -45.928,-30.127 -45.928,-28.945 -45.469,-28.486 U2.2@-45.469,-27.305
NetC93_1: C93.1 R9.1 R11.2 U2.6 | length 7.2
  Top Layer (PADS/SIG) w0.254: U2.6@-43.469,-27.305 -43.446,-27.328 -43.446,-27.936 -43.208,-28.174 -41.663,-28.174 -41.643,-28.194 C93.1@-40.894,-28.194 ; C93.1@-40.81,-28.323 -40.173,-27.686 R9.1@-39.394,-27.686 ; R9.1@-39.394,-27.755 -37.846,-26.207 R11.2@-37.846,-26.162
NetC94_1: C94.1 R12.1 R13.1 U2.10 | length 7.2
  Top Layer (PADS/SIG) w0.254: R13.1@-45.856,-19.332 R12.1@-44.295,-19.332 ; -44.45,-22.098 -44.069,-22.479 C94.1@-43.942,-22.479 ; -44.44,-22.076 -44.44,-20.544 -44.218,-20.321 R12.1@-44.218,-19.332 ; U2.10@-43.969,-24.305 -43.969,-22.506 C94.1@-43.942,-22.479 ; C94.1@-43.688,-22.479 C94.1@-43.942,-22.479
NetC95_1: C95.1 R14.1 R15.2 U2.9 | length 8.4
  Top Layer (PADS/SIG) w0.254: U2.9@-43.469,-24.305 -43.469,-23.548 -42.936,-23.014 -42.936,-22.997 C95.1@-42.482,-22.543 ; C95.1@-42.436,-22.527 -42.418,-22.545 C95.1@-42.418,-22.606 ; C95.1@-42.291,-22.606 -41.684,-21.999 -41.684,-20.291 R14.1@-42.643,-19.332 -41.092,-17.78 R15.2@-41.021,-17.78
NetC104_2: C104.2 U101.17 | length 5
  Top Layer (PADS/SIG) w0.254: U101.17@-137.181,-32.831 -137.083,-32.733 -136.325,-32.733 -135.729,-32.138 C104.2@-135.729,-28.853
NetC105_2: C105.2 U101.5 | length 3
  Top Layer (PADS/SIG) w0.254: U101.5@-131.381,-34.781 -131.283,-34.879 -130.356,-34.879 -129.623,-35.613 C105.2@-128.678,-35.613
NetC106_1: C106.1 U101.22 | length 3.9
  Top Layer (PADS/SIG) w0.254: C106.1@-140.174,-38.251 -138.004,-36.081 U101.22@-137.181,-36.081
NetC109_2: C109.2 U101.20 | length 3.2
  Top Layer (PADS/SIG) w0.254: C109.2@-140.174,-35.203 -139.752,-34.781 U101.20@-137.181,-34.781
NetC110_1: C110.1 R111.1 U101.18 | length 5.1
  Top Layer (PADS/SIG) w0.254: R111.1@-140.174,-30.631 -140.174,-32.155 -138.848,-33.481 U101.18@-137.181,-33.481
NetC111_1: C111.1 R112.1 | length 1.4
  Top Layer (PADS/SIG) w0.254: R112.1@-133.985,-38.862 -133.923,-38.924 C111.1@-132.588,-38.924
NetC112_1: C112.1 R112.2 U101.24 | length 4.4
  Top Layer (PADS/SIG) w0.254: U101.24@-137.181,-37.381 -137.107,-37.381 C112.1@-135.551,-38.937 -135.45,-38.937 R112.2@-134.027,-40.36
NetC117_1: C117.1 D106.1 D109.2 Q105.3 T103.7
NetC117_2: C117.2 R117.2 R119.2
NetC118_1: C118.1 D107.1 D110.2 Q106.3 T103.11 | length 14.9
  Top Layer (PADS/SIG) w0.762: Q106.3@-119.477,-13.256 -111.404,-13.256 T103.11@-110.957,-13.703 -108.095,-10.84 D110.2@-108.095,-8.703
NetC118_2: C118.2 R118.2 R120.2 | length 6.8
  Top Layer (PADS/SIG) w0.762: C118.2@-118.069,-3.623 -115.159,-6.533 R118.2@-115.159,-9.248
NetC122_1: C122.1 D109.1 D110.1 R121.1 R301.1
NetC127_1: C127.1 U8.9 | length 4.4
  Top Layer (PADS/SIG) w0.254: C127.1@-64.739,-24.935 -63.912,-24.108 -62.605,-24.108 -62.413,-24.3 -62.413,-24.838 U8.9@-61.306,-24.838
NetC128_2: C128.2 R73.2 | length 1.9
  Top Layer (PADS/SIG) w0.254: R73.2@-61.561,-28.392 -60.232,-28.392 C128.2@-59.833,-27.993
NetC129_1: C129.1 U8.16 | length 1.7
  Top Layer (PADS/SIG) w0.254: U8.16@-55.506,-24.838 -53.991,-24.838 C129.1@-53.871,-24.718
NetC201_1: C201.1 R201.2 R207.1 U201.18 | length 12.6
  Top Layer (PADS/SIG) w0.254: R207.1@-132.944,-47.3 R201.2@-132.944,-48.723 -134.185,-49.963 -134.861,-49.963 -135.052,-50.155 -135.052,-51.188 -134.854,-51.386 -133.415,-51.386 -133.391,-51.41 -133.358,-51.41 C201.1@-132.885,-51.883 ; C201.1@-132.78,-51.883 C201.1@-132.78,-52.183 -132.78,-52.708 -132.457,-53.031 -131.671,-53.031 -130.331,-54.371 U201.18@-129.314,-54.371
NetC202_2: C202.2 U201.17 | length 3.1
  Top Layer (PADS/SIG) w0.254: C202.2@-131.393,-52.094 -131.393,-52.651 -130.195,-53.848 -129.337,-53.848 U201.17@-129.314,-53.871
NetC203_1: C203.1 D201.1 D202.1 U201.8 | length 9.2
  Top Layer (PADS/SIG) w0.254: U201.8@-129.314,-49.371 -129.337,-49.348 -130.195,-49.348 -130.416,-49.128 -130.416,-47.929 -130.756,-47.589 -130.756,-47.58 -131.035,-47.3 C203.1@-131.366,-47.3 -131.153,-47.087 D201.1@-131.153,-45.209 -129.658,-43.714 D202.1@-128.326,-43.714
NetC204_1: C204.1 U201.48 U201.49 U201.50 | length 4.4
  Top Layer (PADS/SIG) w0.254: U201.48@-121.814,-49.871 -120.774,-49.871 -120.774,-49.371 ; U201.49@-121.814,-49.371 -120.774,-49.371 ; U201.50@-121.455,-48.848 -120.934,-48.848 -120.774,-49.008 -120.774,-49.371 ; C204.1@-120.058,-49.47 -120.157,-49.371 -120.774,-49.371
NetC205_2: C205.2 R202.1 R206.2 U201.33 U201.34 U201.35 | length 26.6
  Top Layer (PADS/SIG) w0.254: v1(-134.344,-54.534) R206.2@-132.9,-54.534 ; U201.33@-121.814,-57.371 -120.817,-57.371 ; U201.34@-121.814,-56.871 -121.773,-56.913 -120.817,-56.913 ; U201.35@-121.814,-56.371 -120.9,-56.371 -120.817,-56.454 -120.817,-56.913 ; v1(-120.064,-56.91) -120.356,-56.91 -120.817,-57.371 ; -120.817,-57.371 -120.817,-56.913
  Layer 4 (SIG) w0.254: v1(-134.344,-54.534) -134.344,-57.094 -130.312,-61.126 -124.279,-61.126 v1(-120.064,-56.91)
NetC206_1: C206.1 R214.2 R220.1 U202.18 | length 11.3
  Top Layer (PADS/SIG) w0.254: U202.18@-82.735,-63.908 -81.74,-63.908 -80.986,-64.662 -80.005,-64.662 ; -79.941,-64.725 -79.16,-65.506 C206.1@-79.16,-65.538 ; C206.1@-79.16,-65.626 -78.446,-66.341 -77.044,-66.341 -76.852,-66.532 -76.852,-67.565 -77.522,-68.235 R220.1@-77.522,-68.987 R214.2@-79.148,-68.987 ; C206.1@-79.066,-65.443 C206.1@-79.037,-65.472
NetC207_2: C207.2 U202.17 | length 2.3
  Top Layer (PADS/SIG) w0.25: U202.17@-82.735,-64.408 -82.735,-64.433 -81.854,-64.433 C207.2@-80.911,-65.376 ; C207.2@-80.76,-65.626 C207.2@-80.76,-65.524
NetC208_1: C208.1 D203.1 D204.1 U202.8 | length 7.8
  Top Layer (PADS/SIG) w0.254: D204.1@-82.847,-74.362 -80.815,-72.33 D203.1@-80.688,-72.33 ; U202.8@-82.735,-68.908 -82.712,-68.931 -81.854,-68.931 -81.577,-69.207 -81.577,-70.171 -81.323,-70.425 C208.1@-80.942,-70.425 ; C208.1@-80.92,-70.552 -80.92,-71.954 D203.1@-80.62,-72.255
NetC209_1: C209.1 U202.48 U202.49 U202.50 | length 4.6
  Top Layer (PADS/SIG) w0.254: C209.1@-91.985,-68.869 -91.946,-68.908 -91.149,-68.908 ; U202.50@-90.235,-69.408 -91.1,-69.408 -91.149,-69.359 -91.149,-68.908 ; U202.49@-90.235,-68.908 -91.149,-68.908 ; U202.48@-90.235,-68.408 -91.141,-68.408 -91.149,-68.416 -91.149,-68.908
NetC210_2: C210.2 R216.1 R219.2 U202.33 U202.34 U202.35 | length 27.9
  Top Layer (PADS/SIG) w0.254: C210.2@-91.985,-61.369 -91.946,-61.408 -91.12,-61.408 ; U202.35@-90.235,-61.908 -91.052,-61.908 -91.12,-61.84 -91.12,-61.408 ; U202.34@-90.235,-61.408 -91.12,-61.408 ; U202.33@-90.235,-60.908 -91.105,-60.908 -91.12,-60.923 -91.12,-61.408 ; R219.2@-78.97,-63.83 v1(-77.538,-63.83)
  Layer 4 (SIG) w0.254: v1(-91.966,-61.4) -91.966,-58.603 -91.497,-58.135 -79.548,-58.135 -77.538,-60.144 v1(-77.538,-63.83)
NetC211_1: C211.1 R227.2 U203.8 U203.18 | length 17
  Top Layer (PADS/SIG) w0.254: R227.2@-139.767,-11.984 -140.475,-11.276 -141.706,-11.276 -142.17,-11.74 -142.17,-14.013 -141.978,-14.204 -140.595,-14.204 -139.767,-15.032 -138.768,-15.032 -138.582,-15.218 -138.582,-17.873 -138.173,-18.281 -136.933,-18.281 U203.18@-136.933,-18.304 ; R227.2@-139.616,-11.984 -139.153,-11.984 -137.833,-13.304 U203.8@-136.933,-13.304
NetC212_2: C212.2 U203.17 | length 6.7
  Top Layer (PADS/SIG) w0.254: C212.2@-139.767,-13.508 -138.829,-13.508 -138.128,-14.209 -138.128,-17.685 -138.031,-17.781 -136.956,-17.781 U203.17@-136.933,-17.804
NetC213_2: C213.2 U203.48 U203.49 U203.50 | length 3.6
  Top Layer (PADS/SIG) w0.254: U203.48@-129.433,-13.804 -128.576,-13.804 -128.572,-13.8 -128.572,-13.336 ; U203.50@-129.433,-12.804 -128.64,-12.804 -128.572,-12.873 -128.572,-13.336 ; C213.2@-127.683,-13.343 -127.689,-13.336 -128.572,-13.336
NetC214_2: C214.2 R228.2 R229.1 U203.33 U203.34 U203.35 | length 23.5
  Top Layer (PADS/SIG) w0.254: v1(-141.19,-19.579) R229.1@-141.19,-18.055 ; U203.33@-129.433,-21.304 -128.604,-21.304 -128.572,-21.272 -128.572,-20.804 ; U203.34@-129.433,-20.804 -128.572,-20.804 ; U203.35@-129.433,-20.304 -128.685,-20.304 -128.572,-20.417 -128.572,-20.804 ; v1(-127.683,-20.843) -127.721,-20.804 -128.572,-20.804
  Layer 4 (SIG) w0.254: v1(-141.19,-19.579) -136.434,-24.335 -130.041,-24.335 -127.683,-21.977 v1(-127.683,-20.843)
NetC305_2: C305.2 R204.1 U201.24 | length 4
  Top Layer (PADS/SIG) w0.254: C305.2@-131.488,-59.63 R204.1@-131.488,-58.36 ; R204.1@-131.45,-58.206 -131.488,-58.243 R204.1@-131.488,-58.36 ; U201.24@-129.314,-57.371 -130.172,-57.371 -131.161,-58.36 R204.1@-131.488,-58.36
NetC306_2: C306.2 R217.1 U202.24 | length 4.9
  Top Layer (PADS/SIG) w0.254: U202.24@-82.735,-60.908 -81.712,-60.908 -80.815,-60.011 -80.434,-60.011 C306.2@-80.307,-59.884 ; C306.2@-80.264,-59.927 R217.1@-78.835,-58.499
NetD1_3: D1.3 L1.1 U4.23 U4.24 U4.25 U4.26 U4.27 U4.28 U4.29 U4.30 U4.31 U4.32 U4.33 U4.34
NetD2_3: D2.3 L2.1 U7.23 U7.24 U7.25 U7.26 U7.27 U7.28 U7.29 U7.30 U7.31 U7.32 U7.33 U7.34
NetD3_1: D3.1 D4.1 Q101.3 Q103.3 T102.2 | length 25
  Bottom Layer (PAD/SIG) w1.524: D3.1@-118.564,-46.552 -118.564,-45.205 -115.717,-42.358 -109.852,-42.358 v1(-109.663,-42.546) ; v1(-103.771,-71) -103.771,-71.381 -101.526,-73.626 -93.96,-73.626 D4.1@-93.96,-71.243
NetD6_2: D6.2 T1.10 | length 5.1
  Top Layer (PADS/SIG) w1.27: D6.2@-68.179,-34.684 -67.346,-34.684 -67.346,-35.133 -64.954,-35.133 T1.10@-63.924,-34.103
NetD7_2: D7.2 D8.2 T1.1 | length 5.8
  Top Layer (PADS/SIG) w0.762: -64.28,-52.3 -64.28,-52.467 D8.2@-63.451,-53.297
  Top Layer (PADS/SIG) w1.27: D7.2@-66.017,-54.037 -64.28,-52.3 -63.761,-51.781 T1.1@-63.761,-50.492
NetD101_2: D101.2 D103.1 T102.4 | length 9.4
  Top Layer (PADS/SIG) w0.762: D101.2@-142.55,-77.825 D103.1@-140.482,-77.825 ; -141.498,-77.698 -137.6,-77.698 -136.872,-78.426 T102.4@-134.465,-78.426
NetD102_1: D102.1 R103.2 R111.2 | length 44.3
  Top Layer (PADS/SIG) w0.762: R103.2@-143.15,-72.283 -142.662,-71.795 v1(-142.662,-70.241)
  Layer 4 (SIG) w0.254: v1@-142.664,-70.298 -141.34,-68.974 -141.34,-43.768 -141.016,-43.444 -141.016,-33.439 -141.394,-33.06 v1(-141.394,-30.608) ; v1@-142.664,-70.171 -141.594,-69.101
NetD102_2: D102.2 D104.1 T102.3 | length 10.1
  Top Layer (PADS/SIG) w0.762: D102.2@-142.662,-66.971 D104.1@-140.407,-66.971 ; -141.423,-66.844 -137.396,-66.844 -136.923,-66.372 -136.923,-65.726 T102.3@-134.465,-65.726
NetD105_2: D105.2 R113.2 U101.14 | length 8.7
  Top Layer (PADS/SIG) w0.254: U101.14@-137.181,-30.881 -137.181,-30.783 -138.038,-30.783 -138.258,-30.563 -138.258,-27.611 -138.019,-27.372 D105.2@-136.822,-27.372 ; D105.2@-136.9,-27.294 D105.2@-136.52,-26.913 -136.52,-25.624 R113.2@-135.704,-24.808
NetD108_2: D108.2 R114.2 U101.15 | length 7.4
  Top Layer (PADS/SIG) w0.254: D108.2@-139.945,-28.57 -138.721,-29.794 -138.721,-31.403 -138.593,-31.531 U101.15@-137.181,-31.531 ; D108.2@-139.623,-28.461 -139.623,-28.184 R114.2@-138.07,-26.631
NetD111_2: D111.2 L102.2 Q107.3 | length 4.3
  Top Layer (PADS/SIG) w0.254: Q107.3@-142.979,-56.061 -140.619,-56.061 -140.505,-55.947 D111.2@-140.505,-57.725
NetD112_2: D112.2 L103.2 Q108.3 | length 10.3
  Top Layer (PADS/SIG) w0.254: D112.2@-83.609,-42.234 -83.609,-43.755 -82.974,-44.39 -81.577,-44.39 ; D112.2@-83.482,-42.231 -83.351,-42.1 -83.351,-40.838 -81.95,-39.437 Q108.3@-79.037,-39.437 Q108.3@-78.91,-39.437
NetD113_2: D113.2 L102.4 R122.2 | length 7.7
  Top Layer (PADS/SIG) w0.254: R122.2@-137.736,-50.613 -137.736,-52.112 -137.33,-52.518 ; R122.2@-137.711,-50.359 -137.711,-48.689 -137.059,-48.037 -136.659,-48.037 -136.314,-47.692 D113.2@-136.314,-45.547
NetD114_2: D114.2 L103.4 R123.2 | length 6.7
  Top Layer (PADS/SIG) w0.254: R123.2@-79.676,-51.768 -79.676,-50.871 -78.529,-49.724 D114.2@-77.64,-49.724 ; -78.656,-46.93 -78.275,-46.93 -77.64,-47.565 D114.2@-77.64,-49.597
NetD201_2: D201.2 R207.2 | length 2.1
  Top Layer (PADS/SIG) w0.254: R207.2@-134.367,-47.3 -134.253,-47.186 D201.2@-134.253,-45.209
NetD203_2: D203.2 R220.2 | length 1.9
  Top Layer (PADS/SIG) w0.254: R220.2@-77.522,-70.409 R220.2@-77.374,-70.557 ; D203.2@-77.52,-72.255 R220.2@-77.52,-70.538
"NetFull Bridge Bode_2": "Full Bridge Bode.2" R124.1 R125.2 | length 11
  Top Layer (PADS/SIG) w0.254: -142.918,-45.279 -142.791,-45.406 v1(-140.759,-45.406) -139.942,-44.589 -139.942,-40.398 -139.235,-39.691 ; -139.203,-39.652 -137.783,-39.652 v1(-137.075,-40.36)
NetL3_1: L3.1 T2.3
NetL101_1: L101.1 T103.9 | length 6.6
  Top Layer (PADS/SIG) w0.508: T103.9@-103.337,-13.703 -100.883,-13.703 v1(-100.881,-13.704) ; v1@-89.253,-13.598 -86.254,-13.598 L101.1@-85.456,-12.8
  other v1: -100.881,-20.027 -99.738,-20.027 -100.881,-18.973 -99.738,-18.973 -90.75,-18.911 -89.253,-18.911 -100.881,-17.919 -99.738,-17.919 -90.75,-17.857 -89.253,-17.857 -100.881,-16.866 -99.738,-16.866 -90.75,-16.804 -89.253,-16.804 -100.881,-15.812 -99.738,-15.812 -90.75,-15.75 -89.253,-15.75 -100.881,-14.758 -99.738,-14.758 -90.75,-14.696 -89.253,-14.696 -99.738,-13.704 -90.75,-13.642 -89.253,-13.642 -100.881,-12.651 -99.738,-12.651 -90.75,-12.589 -89.253,-12.589
NetL102_1: L102.1 Q107.1 R115.1 | length 3.7
  Top Layer (PADS/SIG) w0.254: Q107.1@-142.029,-53.661 -140.378,-52.01 R115.1@-140.378,-50.724 R115.1@-140.378,-50.613
NetL103_1: L103.1 Q108.1 R116.1 | length 8.4
  Top Layer (PADS/SIG) w0.254: Q108.1@-79.987,-41.837 -79.926,-41.898 -79.926,-42.866 -78.783,-44.009 ; L103.1@-78.529,-44.009 -78.783,-44.009 ; R116.1@-75.862,-41.85 -75.862,-44.009 -76.37,-44.517 -78.275,-44.517 -78.783,-44.009
NetL301_2: L301.2 T103.5 T103.6
NetLDO_BODE_1: LDO_BODE.1 R31.1 R71.1 | length 4.1
  Top Layer (PADS/SIG) w0.254: LDO_BODE.1@-57.529,-29.016 -55.704,-29.016 R71.1@-55.155,-29.565 -55.155,-31.011 R31.1@-55.18,-31.036
"NetMSP430 JTAG_2": "MSP430 JTAG.2" "MSP430 Tool/Target.3" | length 20.8
  Layer 4 (SIG) w0.254: -143.426,-13.402 -142.029,-12.005 -142.029,-11.37 ; -142.034,-11.365 -137.21,-6.54 -130.98,-6.54 -130.082,-5.642 -130.082,-4.249 -128.694,-2.861 -128.694,-2.607 ; -128.694,-2.48 -128.44,-2.48
"NetMSP430 JTAG_4": "MSP430 JTAG.4" "MSP430 Tool/Target.1" | length 15.7
  Layer 4 (SIG) w0.254: -143.426,-8.989 -140.301,-8.989 -137.656,-6.345 -137.656,-4.956 -137.466,-4.766 ; -137.514,-4.718 -136.791,-3.995 -132.622,-3.995 -131.234,-2.607
NetQ2_1: Q2.1 R51.2 R55.2 R56.2 | length 5.3
  Top Layer (PADS/SIG) w1.27: Q2.1@-54.7,-55.696 -55.323,-56.319 R55.2@-55.323,-57.652 R51.2@-53.799,-57.652 R56.2@-52.229,-57.652
NetQ2_3: Q2.3 Q2.4 R56.1 R57.1 R58.2 | length 7.7
  Top Layer (PADS/SIG) w1.27: Q2.3@-52.897,-55.544 -52.621,-55.82 R58.2@-50.843,-55.82 ; Q2.3@-52.897,-55.461 Q2.4@-52.897,-53.626 ; R56.1@-50.735,-57.447 R58.2@-50.735,-55.696 ; R56.1@-50.462,-57.852 -49.725,-58.589 R57.1@-49.725,-59.505
NetQ3_1: Q3.1 Q3.3 R16.1 | length 71.9
  Top Layer (PADS/SIG) w0.508: Q3.1@-126.921,-7.941 Q3.1@-126.921,-7.306 ; Q3.1@-126.916,-7.306 -125.966,-6.356 Q3.3@-125.966,-5.641 ; Q3.1@-126.728,-7.955 Q3.1@-126.728,-7.941
  Layer 4 (SIG) w0.508: v1(-126.789,-8.322) -126.027,-9.084 -124.122,-9.084 ; -124.122,-9.03 -97.379,-9.03 -97.325,-9.084 ; -97.232,-8.991 -95.224,-10.999 -95.224,-22.449 -94.499,-23.174 -86.58,-23.174 -85.599,-24.155 ; -85.614,-24.17 -85.2,-24.585 -85.2,-27.944 -85.26,-28.004 -85.26,-29.404 ; -85.2,-29.488 -81.999,-32.689 ; -81.907,-32.782 -81.872,-32.816 v1(-81.872,-37.541)
NetQ3_2: Q3.2 R17.1 | length 68.5
  Layer 4 (SIG) w0.508: v1(-124.884,-8.322) -124.845,-8.283 -97.071,-8.283 ; -96.939,-8.283 -94.516,-10.706 -94.516,-22.156 -94.206,-22.466 -86.286,-22.466 -84.717,-24.035 -84.717,-24.066 -84.492,-24.291 -84.492,-28.963 -84.552,-29.023 ; -84.398,-29.023 -84.398,-29.289 -81.164,-32.523 -81.164,-36.716 v1(-80.394,-37.487)
NetQ109_1: Q109.1 R122.1 | length 9.8
  Top Layer (PADS/SIG) w0.254: R122.1@-136.314,-50.613 -136.314,-51.375 -135.56,-52.129 -135.56,-58.672 -134.79,-59.442 Q109.1@-134.79,-59.757
NetQ110_1: Q110.1 R123.1 | length 2.6
  Top Layer (PADS/SIG) w0.254: Q110.1@-83.482,-51.756 -81.069,-51.756 R123.1@-80.942,-51.629
NetR22_1: R22.1 U8.23 | length 1.6
  Top Layer (PADS/SIG) w0.254: U8.23@-55.506,-20.288 -55.475,-20.256 R22.1@-53.871,-20.256
NetR23_2: R23.2 R27.1 U8.2 | length 3.3
  Top Layer (PADS/SIG) w0.254: R27.1@-64.521,-20.483 -62.997,-20.483 -62.802,-20.288 U8.2@-61.306,-20.288
NetR28_1: R28.1 R71.2 U8.13 | length 3.6
  Top Layer (PADS/SIG) w0.254: U8.13@-55.506,-26.788 -55.155,-27.14 R28.1@-55.155,-27.979 R71.2@-53.568,-29.565
NetR29_1: R29.1 U8.11 | length 2.1
  Top Layer (PADS/SIG) w0.254: R29.1@-63.215,-26.535 -62.879,-26.535 -62.482,-26.138 U8.11@-61.306,-26.138
NetR35_2: R35.2 U4.36 | length 2.4
  Top Layer (PADS/SIG) w0.254: U4.36@-15.704,-12.988 -13.412,-12.988 R35.2@-13.338,-13.062
NetR38_1: R38.1 R40.2 U4.42 | length 5
  Top Layer (PADS/SIG) w0.254: U4.42@-15.704,-9.178 -14.259,-9.178 R40.2@-13.338,-8.256 -13.214,-8.256 R38.1@-11.738,-9.733
NetR41_2: R41.2 U7.36 | length 3
  Top Layer (PADS/SIG) w0.254: U7.36@-29.636,-47.174 -29.636,-46.415 -28.237,-45.016 R41.2@-28.237,-44.771
NetR42_2: R42.2 U4.4 | length 2.4
  Top Layer (PADS/SIG) w0.254: R42.2@-25.433,-9.28 -25.233,-9.28 -24.7,-9.813 U4.4@-23.204,-9.813
NetR43_1: R43.1 R69.1 U7.37 | length 26.6
  Top Layer (PADS/SIG) w0.254: R43.1@-31.255,-57.267 -31.232,-57.267 v1(-29.636,-58.864) R69.1@-29.718,-58.946 ; U7.37@-30.271,-47.174 -30.207,-47.11 -30.207,-46.068 v1@-30.085,-45.946
  Bottom Layer (PAD/SIG) w0.254: v1@-30.085,-45.946 -30.182,-46.042 -30.182,-47.824 -30.405,-48.047 -34.887,-48.047 -35.225,-48.385 -35.225,-53.897 -35.098,-54.024 -30.228,-54.024 -29.587,-54.664 -29.587,-56.705 -29.636,-56.754 v1(-29.636,-58.864)
  other v1: -30.085,-46.042
NetR45_2: R45.2 U4.39 | length 2.5
  Top Layer (PADS/SIG) w0.254: U4.39@-15.704,-11.083 v1@-14.71,-11.083
  Bottom Layer (PAD/SIG) w0.254: v1@-14.71,-11.083 -14.007,-11.083 R45.2@-13.413,-11.677
  other v1: -14.555,-11.275
NetR50_1: R50.1 R53.2 U6.14 | length 5.4
  Top Layer (PADS/SIG) w0.254: R50.1@-61.927,-65.17 R53.2@-61.927,-66.796 -61.13,-66.796 -60.405,-67.52 -59.606,-67.52 ; -59.606,-67.504 -59.424,-67.322 U6.14@-59.424,-66.443
NetR51_1: R51.1 U6.2 U6.3
NetR55_1: R55.1 U6.4 U6.5
NetR68_1: R68.1 R70.2 U7.42 | length 4.8
  Top Layer (PADS/SIG) w0.254: U7.42@-33.446,-47.174 -33.446,-46.249 R68.1@-31.786,-44.59 R70.2@-30.28,-44.59
NetR72_2: R72.2 U7.4 | length 4.2
  Top Layer (PADS/SIG) w0.254: R72.2@-35.327,-57.322 -34.51,-56.506 -33.578,-56.506 -32.811,-55.738 U7.4@-32.811,-54.674
NetR73_1: R73.1 U8.12 | length 2.5
  Top Layer (PADS/SIG) w0.254: R73.1@-63.161,-28.392 -61.557,-26.788 U8.12@-61.306,-26.788
NetR75_2: R75.2 U7.39 | length 3.1
  Top Layer (PADS/SIG) w0.254: v1(-31.656,-46.042) -31.541,-46.158 U7.39@-31.541,-47.174
  Bottom Layer (PAD/SIG) w0.254: v1@-31.565,-45.952 v1(-31.656,-46.042) -31.656,-45.212 R75.2@-30.971,-44.526
NetR79_2: R79.2 U2.12 | length 8.7
  Top Layer (PADS/SIG) w0.254: R79.2@-47.442,-19.316 -47.581,-19.455 -47.581,-24.03 -46.454,-25.157 -44.996,-25.157 -44.992,-25.153 -44.992,-24.305 U2.12@-44.969,-24.305 ; U2.12@-44.969,-24.305 U2.12@-44.946,-24.324
NetR81_1: R81.1 R84.2 U9.12 | length 8.1
  Layer 4 (SIG) w0.254: v1(-51.943,-30.353) -51.943,-28.194 v1(-51.689,-27.94)
  Bottom Layer (PAD/SIG) w0.254: R81.1@-52.113,-31.436 -51.937,-31.26 v1@-51.937,-30.319 ; R84.2@-51.522,-27.686 R84.2@-51.522,-27.432 -51.522,-27.278 -50.038,-25.794 -48.4,-25.794 U9.12@-48.26,-25.654
NetR82_1: R82.1 R83.2 U9.11 | length 5.2
  Layer 4 (SIG) w0.254: v1(-50.038,-30.48) v1@-50.038,-28.067
  Bottom Layer (PAD/SIG) w0.254: v1@-50.165,-30.48 -50.081,-30.564 R82.1@-50.081,-31.665 ; R83.2@-49.911,-27.686 -49.149,-26.924 U9.11@-48.641,-26.924
  other v1: -50.031,-27.993
NetR83_1: R83.1 U9.10 | length 1.5
  Bottom Layer (PAD/SIG) w0.254: R83.1@-49.911,-29.286 -48.946,-28.321 U9.10@-48.768,-28.321
NetR84_1: R84.1 U9.9 | length 3.3
  Bottom Layer (PAD/SIG) w0.254: R84.1@-51.522,-29.286 -51.105,-29.286 -50.546,-29.845 ; -50.521,-29.859 -49.036,-29.859 U9.9@-48.641,-29.464
NetR101_2: R101.2 U101.2 | length 3.5
  Top Layer (PADS/SIG) w0.254: U101.2@-131.381,-36.731 -131.283,-36.829 -130.423,-36.829 -129.84,-37.412 -129.84,-37.841 -129.455,-38.226 R101.2@-129.455,-38.937
NetR102_2: R102.2 U101.3 | length 4.9
  Top Layer (PADS/SIG) w0.254: U101.3@-131.381,-36.081 -130.529,-36.081 -129.386,-37.224 -129.386,-37.653 -128.102,-38.937 R102.2@-127.931,-38.937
